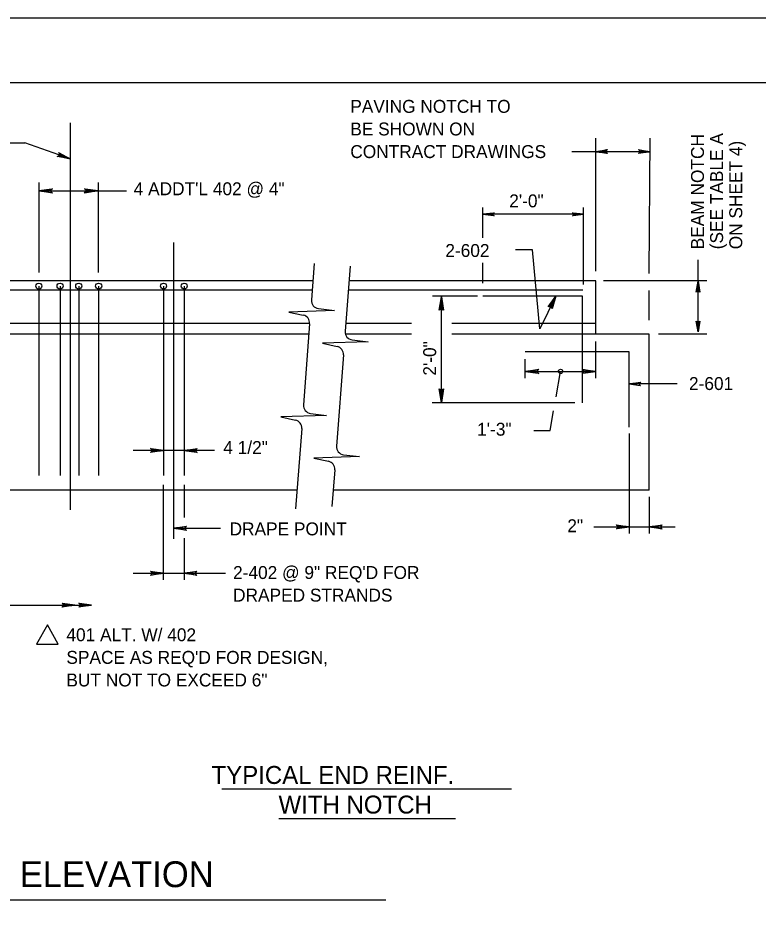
# Model space of a CAD drawing. Extents: x 637933 to 640019, y 298854 to 300042.
# Drawn here: x 638217.1 to 638388.8, y 299833.4 to 300042.1 of the extents above; entities that cross this region are included whole.
import ezdxf

# ---------------------------------------------------------------- set-up
doc = ezdxf.new("R2010")
doc.units = 0
doc.layers.add('1', color=7, linetype='Continuous')
doc.layers.add('PLT-BNDY', color=7, linetype='Continuous')

msp = doc.modelspace()

# ---------------------------------------------------------------- linework, layer by layer
at = {"layer": '1'}
for p, q in [((638023.93, 300027.12), (638809.94, 300027.12)), ((638229.15, 300017.8), (638229.15, 299927.92)), ((638351.21, 299983.36), (638351.21, 300014.25)), ((638363.58, 299982.82), (638363.77, 300014.18)), ((638212.91, 300013.17), (638218.62, 300013.17)), ((638229.15, 300009.41), (638218.62, 300013.17)), ((638351.21, 300011.05), (638345.65, 300011.05)), ((638363.75, 300011.05), (638351.21, 300011.05)), ((638221.91, 300003.9), (638221.91, 299983.01)), ((638235.66, 300003.9), (638235.66, 299983.01)), ((638221.91, 300001.97), (638242.26, 300001.97)), ((638324.96, 299991.09), (638324.96, 299998.16)), ((638348.29, 299980.25), (638348.29, 299998.09)), ((638348.29, 299996.54), (638324.96, 299996.54)), ((638253.18, 299989.99), (638253.18, 299921.21)), ((638336.48, 299988.32), (638332.51, 299988.32)), ((638338.21, 299969.99), (638336.48, 299988.32)), ((638285.8, 299985.14), (638285.17, 299976.66)), ((638324.96, 299980.57), (638324.96, 299985.24)), ((638374.96, 299981), (638374.96, 299985.98)), ((638294.14, 299984.49), (638293, 299969.39)), ((638285.53, 299981.12), (638069.71, 299981.12)), ((638351.21, 299981.12), (638294.08, 299981.12)), ((638351.21, 299968.75), (638351.21, 299981.12)), ((638376.96, 299981.12), (638352.96, 299981.12)), ((638374.96, 299969.25), (638374.96, 299981)), ((638101.97, 299979.02), (638285.4, 299979.02)), ((638221.89, 299979.87), (638221.89, 299935.89)), ((638221.89, 299979.87), (638221.89, 299979.87)), ((638221.89, 299979.87), (638221.89, 299979.87)), ((638221.89, 299979.87), (638221.89, 299979.87)), ((638221.89, 299979.87), (638221.89, 299979.87)), ((638226.81, 299979.87), (638226.81, 299935.89)), ((638226.81, 299979.87), (638226.81, 299979.87)), ((638226.81, 299979.87), (638226.81, 299979.87)), ((638226.81, 299979.87), (638226.81, 299979.87)), ((638226.81, 299979.87), (638226.81, 299979.87)), ((638231.15, 299979.87), (638231.15, 299935.89)), ((638231.15, 299979.87), (638231.15, 299979.87)), ((638231.15, 299979.87), (638231.15, 299979.87)), ((638231.15, 299979.87), (638231.15, 299979.87)), ((638231.15, 299979.87), (638231.15, 299979.87)), ((638235.78, 299979.87), (638235.78, 299935.89)), ((638235.78, 299979.87), (638235.78, 299979.87)), ((638235.78, 299979.87), (638235.78, 299979.87)), ((638235.78, 299979.87), (638235.78, 299979.87)), ((638235.78, 299979.87), (638235.78, 299979.87)), ((638250.84, 299979.87), (638250.84, 299935.89)), ((638250.84, 299979.87), (638250.84, 299979.87)), ((638250.84, 299979.87), (638250.84, 299979.87)), ((638250.84, 299979.87), (638250.84, 299979.87)), ((638250.84, 299979.87), (638250.84, 299979.87)), ((638255.64, 299979.87), (638255.64, 299935.89)), ((638255.64, 299979.87), (638255.64, 299979.87)), ((638255.64, 299979.87), (638255.64, 299979.87)), ((638255.64, 299979.87), (638255.64, 299979.87)), ((638255.64, 299979.87), (638255.64, 299979.87)), ((638293.79, 299979.02), (638348.17, 299979.02)), ((638363.58, 299971.94), (638363.58, 299978.86)), ((638323.71, 299977.5), (638313.24, 299977.5)), ((638315.33, 299952.88), (638315.33, 299977.38)), ((638348.08, 299977.5), (638324.96, 299977.5)), ((638341.92, 299977.5), (638338.21, 299969.99)), ((638348.08, 299952.75), (638348.08, 299977.5)), ((638286.81, 299974.66), (638290.54, 299974.2)), ((638290.54, 299974.2), (638279.93, 299973.86)), ((638279.93, 299973.86), (638283.28, 299973.13)), ((638284.5, 299971.19), (638069.71, 299971.19)), ((638284.75, 299971.15), (638283.33, 299952.32)), ((638308.4, 299971.19), (638293.05, 299971.19)), ((638351.21, 299971.19), (638317.77, 299971.19)), ((638284.5, 299968.75), (638069.71, 299968.75)), ((638308.4, 299968.75), (638293.05, 299968.75)), ((638363.58, 299968.75), (638317.77, 299968.75)), ((638363.58, 299968.75), (638351.21, 299968.75)), ((638363.58, 299932.48), (638363.58, 299968.75)), ((638376.96, 299968.75), (638365.71, 299968.75)), ((638298.37, 299966.94), (638287.77, 299966.59)), ((638287.77, 299966.59), (638291.12, 299965.86)), ((638294.64, 299967.39), (638298.37, 299966.94)), ((638351.21, 299958.53), (638351.21, 299967.01)), ((638358.96, 299964.62), (638334.8, 299964.62)), ((638358.96, 299947.12), (638358.96, 299964.62)), ((638292.58, 299963.89), (638290.99, 299942.74)), ((638334.8, 299958.53), (638334.8, 299962.88)), ((638334.8, 299960.07), (638351.21, 299960.07)), ((638341.95, 299954.19), (638343, 299960.07)), ((638370.1, 299957.19), (638358.96, 299957.19)), ((638346.33, 299952.75), (638313.21, 299952.75)), ((638288.7, 299949.86), (638278.1, 299949.52)), ((638278.1, 299949.52), (638281.45, 299948.78)), ((638284.97, 299950.32), (638288.7, 299949.86)), ((638340.56, 299946.39), (638341.36, 299950.88)), ((638282.91, 299946.81), (638281.5, 299928.15)), ((638336.82, 299946.39), (638340.56, 299946.39)), ((638358.96, 299945.62), (638358.96, 299922.47)), ((638262.68, 299941.71), (638243.78, 299941.71)), ((638296.36, 299940.28), (638285.75, 299939.94)), ((638285.75, 299939.94), (638289.1, 299939.21)), ((638292.63, 299940.74), (638296.36, 299940.28)), ((638290.57, 299937.23), (638289.93, 299928.73)), ((638250.8, 299911.7), (638250.8, 299933.75)), ((638255.6, 299933.75), (638255.6, 299926.13)), ((638281.83, 299932.48), (638069.71, 299932.48)), ((638363.58, 299932.48), (638290.21, 299932.48)), ((638363.58, 299930.98), (638363.58, 299922.47)), ((638253.18, 299923.64), (638264.06, 299923.64)), ((638350.71, 299923.97), (638369.58, 299923.97)), ((638255.6, 299921.33), (638255.6, 299911.7)), ((638243.78, 299913.2), (638265.19, 299913.2)), ((638250.8, 299912.16), (638250.8, 299913.2)), ((638142.98, 299905.82), (638234.15, 299905.82)), ((638331.6, 299863.05), (638264.41, 299863.05)), ((638318.58, 299856.18), (638277.64, 299856.18)), ((638302.47, 299837.29), (638123.33, 299837.29))]:
    msp.add_line(p, q, dxfattribs=at)
for points in [[(638226.58, 300010.71), (638226.61, 300010.48), (638229.15, 300009.41), (638226.58, 300010.71), (638226.49, 300010.87), (638229.15, 300009.41), (638226.52, 300010.2), (638226.36, 300010.05), (638229.15, 300009.41), (638226.17, 300009.97), (638226.36, 300010.05)], [(638353.58, 300010.8), (638353.46, 300010.92), (638351.21, 300011.05), (638353.58, 300010.8), (638353.71, 300010.67), (638351.21, 300011.05), (638353.46, 300011.17), (638353.58, 300011.42), (638351.21, 300011.05), (638353.71, 300011.55), (638353.58, 300011.42)], [(638353.75, 300010.8), (638353.62, 300010.92), (638351.37, 300011.05), (638353.75, 300010.8), (638353.87, 300010.67), (638351.37, 300011.05), (638353.62, 300011.17), (638353.75, 300011.42), (638351.37, 300011.05), (638353.87, 300011.55), (638353.75, 300011.42)], [(638361.25, 300011.42), (638361.37, 300011.17), (638363.75, 300011.05), (638361.25, 300011.42), (638361.12, 300011.55), (638363.75, 300011.05), (638361.37, 300010.92), (638361.25, 300010.8), (638363.75, 300011.05), (638361.12, 300010.67), (638361.25, 300010.8)], [(638224.91, 300001.59), (638224.78, 300001.84), (638221.91, 300001.97), (638224.91, 300001.59), (638225.03, 300001.47), (638221.91, 300001.97), (638224.78, 300002.22), (638224.91, 300002.34), (638221.91, 300001.97), (638225.03, 300002.47), (638224.91, 300002.34)], [(638232.66, 300002.34), (638232.78, 300002.22), (638235.66, 300001.97), (638232.66, 300002.34), (638232.53, 300002.47), (638235.66, 300001.97), (638232.78, 300001.84), (638232.66, 300001.72), (638235.66, 300001.97), (638232.53, 300001.47), (638232.66, 300001.72)], [(638327.46, 299996.29), (638327.33, 299996.41), (638324.96, 299996.54), (638327.46, 299996.29), (638327.58, 299996.16), (638324.96, 299996.54), (638327.33, 299996.66), (638327.46, 299996.79), (638324.96, 299996.54), (638327.58, 299996.91), (638327.46, 299996.79)], [(638345.91, 299996.79), (638345.91, 299996.66), (638348.29, 299996.54), (638345.91, 299996.79), (638345.79, 299996.91), (638348.29, 299996.54), (638345.91, 299996.41), (638345.91, 299996.29), (638348.29, 299996.54), (638345.79, 299996.16), (638345.77, 299996.14)], [(638374.58, 299978.62), (638374.83, 299978.62), (638374.96, 299981), (638374.58, 299978.62), (638374.46, 299978.5), (638374.96, 299981), (638375.08, 299978.62), (638375.21, 299978.62), (638374.96, 299981), (638375.33, 299978.5), (638375.21, 299978.62)], [(638314.96, 299974.38), (638315.08, 299974.5), (638315.33, 299977.38), (638314.96, 299974.38), (638314.83, 299974.25), (638315.33, 299977.38), (638315.46, 299974.5), (638315.71, 299974.38), (638315.33, 299977.38), (638315.83, 299974.25), (638315.71, 299974.38)], [(638340.34, 299975.1), (638340.57, 299975.11), (638341.92, 299977.5), (638340.34, 299975.1), (638340.16, 299975.03), (638341.92, 299977.5), (638340.83, 299974.98), (638340.97, 299974.8), (638341.92, 299977.5), (638341.02, 299974.6), (638340.97, 299974.8)], [(638375.21, 299971.62), (638375.08, 299971.5), (638374.96, 299969.25), (638375.21, 299971.62), (638375.33, 299971.75), (638374.96, 299969.25), (638374.83, 299971.5), (638374.58, 299971.62), (638374.96, 299969.25), (638374.46, 299971.75), (638374.58, 299971.62)], [(638337.8, 299959.7), (638337.67, 299959.95), (638334.8, 299960.07), (638337.8, 299959.7), (638337.92, 299959.57), (638334.8, 299960.07), (638337.67, 299960.2), (638337.8, 299960.45), (638334.8, 299960.07), (638337.92, 299960.57), (638337.8, 299960.45)], [(638348.21, 299960.45), (638348.33, 299960.2), (638351.21, 299960.07), (638348.21, 299960.45), (638348.08, 299960.57), (638351.21, 299960.07), (638348.33, 299959.95), (638348.21, 299959.7), (638351.21, 299960.07), (638348.08, 299959.57), (638348.21, 299959.7)], [(638315.71, 299955.88), (638315.46, 299955.75), (638315.33, 299952.88), (638315.71, 299955.88), (638315.83, 299956), (638315.33, 299952.88), (638315.21, 299955.75), (638314.96, 299955.88), (638315.33, 299952.88), (638314.83, 299956), (638314.96, 299955.88)], [(638361.46, 299956.82), (638361.33, 299957.07), (638358.96, 299957.19), (638361.46, 299956.82), (638361.58, 299956.69), (638358.96, 299957.19), (638361.33, 299957.32), (638361.46, 299957.44), (638358.96, 299957.19), (638361.58, 299957.57), (638361.46, 299957.44)], [(638247.99, 299942.07), (638248.09, 299941.86), (638250.84, 299941.71), (638247.99, 299942.07), (638247.84, 299942.19), (638250.84, 299941.71), (638248.1, 299941.58), (638248, 299941.37), (638250.84, 299941.71), (638247.84, 299941.23), (638248, 299941.37)], [(638258.49, 299941.35), (638258.39, 299941.56), (638255.64, 299941.71), (638258.49, 299941.35), (638258.64, 299941.23), (638255.64, 299941.71), (638258.38, 299941.85), (638258.48, 299942.05), (638255.64, 299941.71), (638258.64, 299942.19), (638258.48, 299942.05)], [(638356.1, 299924.33), (638356.21, 299924.12), (638358.96, 299923.97), (638356.1, 299924.33), (638355.96, 299924.45), (638358.96, 299923.97), (638356.21, 299923.83), (638356.11, 299923.63), (638358.96, 299923.97), (638355.96, 299923.49), (638356.11, 299923.63)], [(638366.43, 299923.61), (638366.33, 299923.82), (638363.58, 299923.97), (638366.43, 299923.61), (638366.58, 299923.48), (638363.58, 299923.97), (638366.33, 299924.1), (638366.43, 299924.31), (638363.58, 299923.97), (638366.58, 299924.44), (638366.43, 299924.31)], [(638256.03, 299923.29), (638255.93, 299923.49), (638253.18, 299923.64), (638256.03, 299923.29), (638256.18, 299923.16), (638253.18, 299923.64), (638255.92, 299923.78), (638256.02, 299923.98), (638253.18, 299923.64), (638256.18, 299924.12), (638256.02, 299923.98)], [(638247.95, 299913.56), (638248.06, 299913.35), (638250.8, 299913.2), (638247.95, 299913.56), (638247.8, 299913.68), (638250.8, 299913.2), (638248.06, 299913.06), (638247.96, 299912.86), (638250.8, 299913.2), (638247.8, 299912.72), (638247.96, 299912.86)], [(638258.45, 299912.84), (638258.35, 299913.05), (638255.6, 299913.2), (638258.45, 299912.84), (638258.6, 299912.72), (638255.6, 299913.2), (638258.35, 299913.33), (638258.45, 299913.54), (638255.6, 299913.2), (638258.6, 299913.68), (638258.45, 299913.54)], [(638227.41, 299906.17), (638227.52, 299905.97), (638230.27, 299905.82), (638227.41, 299906.17), (638227.27, 299906.3), (638230.27, 299905.82), (638227.52, 299905.68), (638227.42, 299905.48), (638230.27, 299905.82), (638227.27, 299905.34), (638227.42, 299905.48)], [(638231.3, 299906.17), (638231.41, 299905.97), (638234.15, 299905.82), (638231.3, 299906.17), (638231.15, 299906.3), (638234.15, 299905.82), (638231.41, 299905.68), (638231.31, 299905.48), (638234.15, 299905.82), (638231.15, 299905.34), (638231.31, 299905.48)]]:
    msp.add_lwpolyline(points, dxfattribs=at)
msp.add_lwpolyline([(638223.88, 299901.23), (638221.38, 299896.78), (638226.38, 299896.78)], close=True, dxfattribs=at)
for centre, radius in [((638221.89, 299979.87), 0.7), ((638226.81, 299979.87), 0.7), ((638231.15, 299979.87), 0.7), ((638235.78, 299979.87), 0.7), ((638250.84, 299979.87), 0.7), ((638255.64, 299979.87), 0.7), ((638343, 299960.07), 0.495)]:
    msp.add_circle(centre, radius, dxfattribs=at)
for centre, start, end in [((638287.04, 299976.52), 175.7051, 263.0749), ((638282.88, 299971.29), 355.6965, 77.6495), ((638294.87, 299969.25), 175.7051, 263.0749), ((638290.71, 299964.03), 355.6965, 77.6495), ((638285.2, 299952.18), 175.7051, 263.0749), ((638281.05, 299946.95), 355.6965, 77.6495), ((638292.86, 299942.6), 175.7051, 263.0749), ((638288.7, 299937.38), 355.6965, 77.6495)]:
    msp.add_arc(centre, 1.88, start, end, dxfattribs=at)
at = {"layer": 'PLT-BNDY'}
msp.add_lwpolyline([(637983.93, 300042.12), (638824.93, 300042.12), (638824.93, 299448.12), (637983.93, 299448.12)], close=True, dxfattribs=at)

# ---------------------------------------------------------------- texts
at = {"layer": '1'}
for s, height, p in [('PAVING NOTCH TO', 3, (638294.19, 300020.1)), ('BE SHOWN ON', 3, (638294.19, 300014.85)), ('CONTRACT DRAWINGS', 3, (638294.19, 300009.6)), ('4 ADDT\'L 402 @ 4"', 3, (638243.91, 300000.97)), ('2\'-0"', 3, (638331.09, 299998.16)), ('2-602', 3, (638316.25, 299986.64)), ('2-601', 3, (638372.81, 299955.75)), ('1\'-3"', 3, (638323.64, 299945.15)), ('4 1/2"', 3, (638264.71, 299940.91)), ('DRAPE POINT', 3, (638266.17, 299922.01)), ('2"', 3, (638344.57, 299922.74)), ('2-402 @ 9" REQ\'D FOR', 3, (638266.98, 299911.88)), ('DRAPED STRANDS', 3, (638266.98, 299906.63)), ('401 ALT. W/ 402', 3, (638228.29, 299897.43)), ("SPACE AS REQ'D FOR DESIGN,", 3, (638228.29, 299892.18)), ('BUT NOT TO EXCEED 6"', 3, (638228.29, 299886.93)), ('TYPICAL END REINF.', 4.1665, (638261.98, 299864.3)), ('WITH NOTCH', 4.167, (638277.53, 299857.43)), ('STANDARD PA I-BEAM - ELEVATION', 6, (638123.38, 299840.34))]:
    msp.add_text(s, height=height, dxfattribs=at).set_placement(p)
for s, p in [('BEAM NOTCH', (638376.29, 299988.42)), ('(SEE TABLE A', (638380.73, 299988.42)), ('ON SHEET 4)', (638385.17, 299988.42)), ('2\'-0"', (638314.12, 299959.08))]:
    msp.add_text(s, height=3, rotation=90, dxfattribs=at).set_placement(p)

doc.saveas('drawing.dxf')
